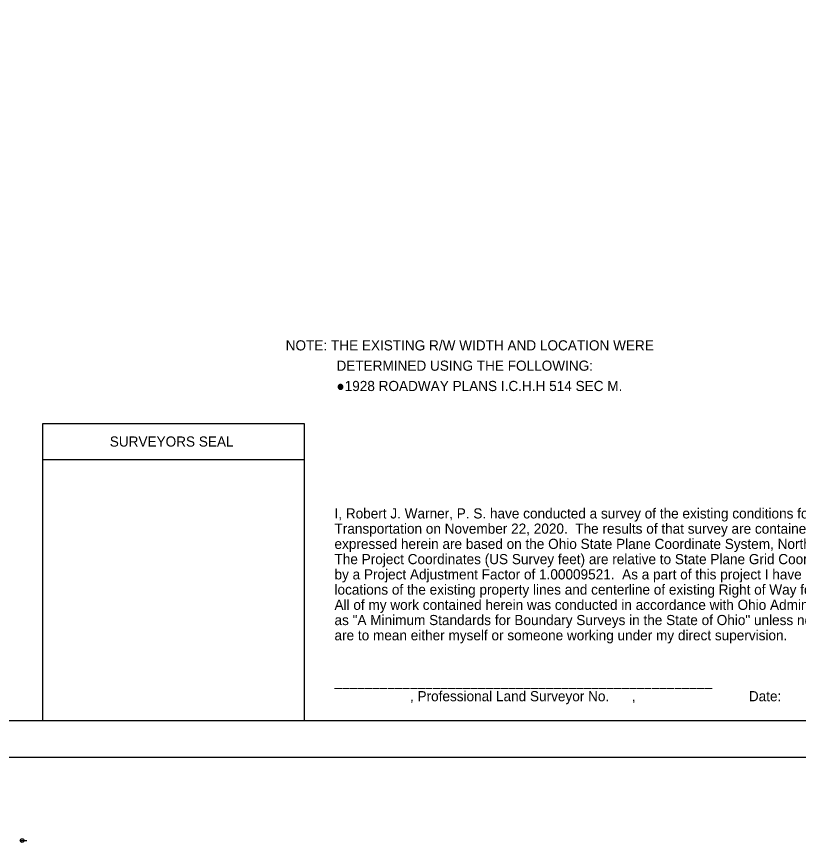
# Model space of a CAD drawing. Extents: x -4.9 to 34, y -1.2 to 22.
# Drawn here: x 16.92 to 27.7, y -1.18 to 10.21 of the extents above; entities that cross this region are included whole.
import ezdxf

# ---------------------------------------------------------------- set-up
doc = ezdxf.new("R2010")
doc.units = 0
for name, color, linetype in [('Default', 7, 'Continuous'), ('SH_Border', 7, 'Continuous'), ('SH_Cut_Line', 7, 'Continuous'), ('SH_Data', 7, 'Continuous'), ('SH_Text', 7, 'Continuous')]:
    doc.layers.add(name, color=color, linetype=linetype)

msp = doc.modelspace()

# ---------------------------------------------------------------- linework, layer by layer
at = {"layer": 'Default'}
for p, q in [((16.974, -1.152), (17.026, -1.152)), ((17, -1.152), (17.064, -1.152))]:
    msp.add_line(p, q, dxfattribs=at)
msp.add_circle((17, -1.152), 0.026, dxfattribs=at)
at = {"layer": 'SH_Border'}
msp.add_lwpolyline([(1.5, 21.5), (33.5, 21.5), (33.5, 0.5), (1.5, 0.5)], close=True, dxfattribs=at)
at = {"layer": 'SH_Cut_Line'}
msp.add_lwpolyline([(0, 0), (34, 0), (34, 22), (0, 22)], close=True, dxfattribs=at)
at = {"layer": 'SH_Data'}
msp.add_line((17.288, 4.1), (20.888, 4.1), dxfattribs=at)
msp.add_lwpolyline([(17.288, 4.6), (20.888, 4.6), (20.888, 0.5), (17.288, 0.5)], close=True, dxfattribs=at)

# ---------------------------------------------------------------- texts
at = {"layer": 'Default'}
for s, p in [('153', (16.996, -1.162)), ('2', (16.999, -1.146)), ('108471_RC001', (17.032, -1.146)), ('1:200', (17.032, -1.162))]:
    msp.add_text(s, height=0.00328, dxfattribs=at).set_placement(p)
at = {"layer": 'SH_Data'}
msp.add_text('SURVEYORS SEAL', height=0.14, dxfattribs=at).set_placement((18.209, 4.28))
at = {"layer": 'SH_Text'}
for s, p in [('NOTE: THE EXISTING R/W WIDTH AND LOCATION WERE ', (20.634, 5.606)), ('DETERMINED USING THE FOLLOWING:', (21.334, 5.326)), ('●1928 ROADWAY PLANS I.C.H.H 514 SEC M.', (21.334, 5.046)), ('I, Robert J. Warner, P. S. have conducted a survey of the existing conditions for the Ohio Department of', (21.307, 3.289)), ('Transportation on November 22, 2020.  The results of that survey are contained herein.  The horizontal coordinates', (21.307, 3.079)), ('expressed herein are based on the Ohio State Plane Coordinate System, North Zone on NAD 83 (2011) datum.', (21.307, 2.869)), ('The Project Coordinates (US Survey feet) are relative to State Plane Grid Coordinates (US Survey feet)', (21.307, 2.659)), ('by a Project Adjustment Factor of 1.00009521.  As a part of this project I have reestablished the', (21.307, 2.449)), ('locations of the existing property lines and centerline of existing Right of Way for property takes contained herein.  ', (21.307, 2.239)), ('All of my work contained herein was conducted in accordance with Ohio Administrative Code 4733-37 commonly known', (21.307, 2.029)), ('as "A Minimum Standards for Boundary Surveys in the State of Ohio" unless noted.  The words I and my as used herein', (21.307, 1.819)), ('are to mean either myself or someone working under my direct supervision.', (21.307, 1.609)), ('__________________________________________________', (21.307, 0.979)), ('                    , Professional Land Surveyor No.      ,                              Date:                ', (21.307, 0.769))]:
    msp.add_text(s, height=0.14, dxfattribs=at).set_placement(p)

doc.saveas('drawing.dxf')
